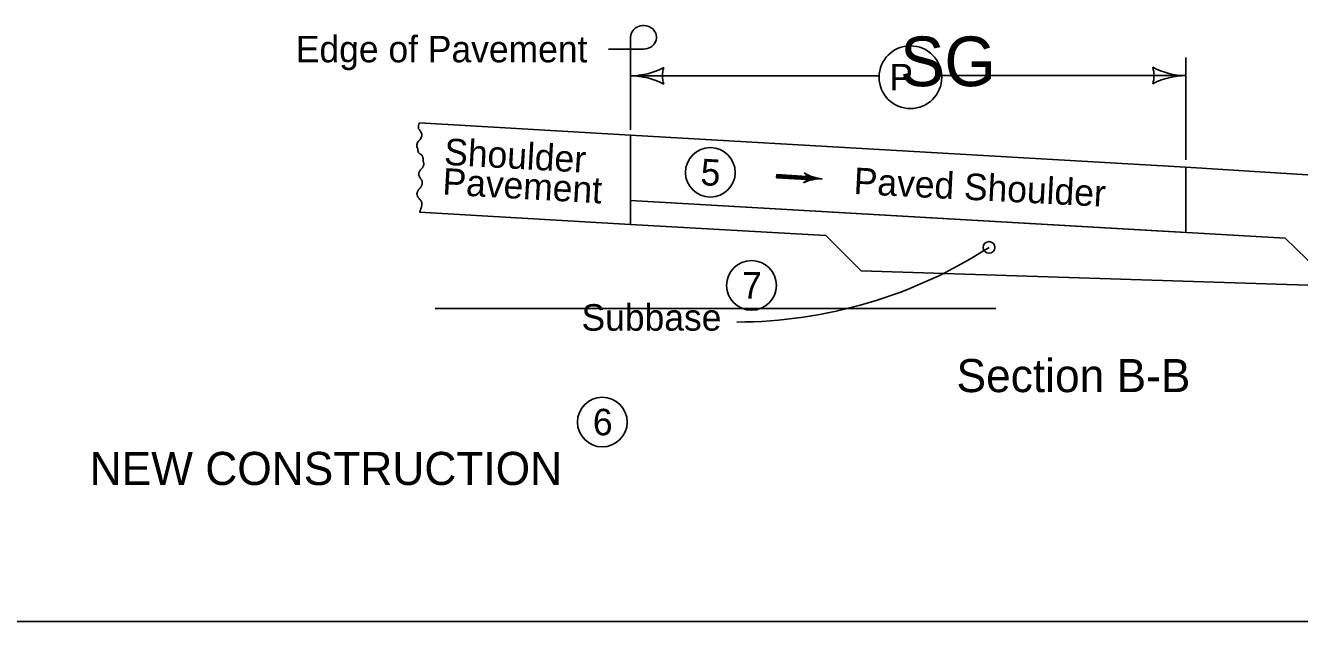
# Model space of a CAD drawing. Extents: x 9538 to 81668, y 7600 to 11751.
# Drawn here: x 18239 to 19008, y 8840 to 9200 of the extents above; entities that cross this region are included whole.
import ezdxf

# ---------------------------------------------------------------- set-up
doc = ezdxf.new("R2010")
doc.units = 0
for name, color, linetype in [('DsnShtMinorGrid13', 7, 'Continuous'), ('DsnShtMinorGrid14', 7, 'Continuous'), ('dsnStdDimension', 7, 'Continuous'), ('dsnStdNameDate', 7, 'Continuous'), ('dsnStdNote', 7, 'Continuous'), ('dsnStdTable', 7, 'Continuous')]:
    doc.layers.add(name, color=color, linetype=linetype)

msp = doc.modelspace()

# ---------------------------------------------------------------- linework, layer by layer
at = {"layer": 'DsnShtMinorGrid13'}
for centre in [(18652.16, 9111.48), (18677.01, 9043.19), (18586.95, 8960.58)]:
    msp.add_circle(centre, 15, dxfattribs=at)
at = {"layer": 'DsnShtMinorGrid14'}
msp.add_circle((18820.4, 9066.08), 3.54, dxfattribs=at)
at = {"layer": 'dsnStdDimension'}
for p, q in [((18939.26, 9119.12), (18939.26, 9180.8)), ((18604.04, 9169.81), (18754.04, 9169.81)), ((18791.86, 9169.96), (18939.26, 9169.96))]:
    msp.add_line(p, q, dxfattribs=at)
msp.add_circle((18772.95, 9168.99), 18.93, dxfattribs=at)
for centre, radius, start, end in [((18604.04, 9212.31), 42.5, 270, 298.07249), ((18604.04, 9127.31), 42.5, 61.92751, 90), ((18639.67, 9169.81), 16.42, 162.26665, 197.73335), ((18903.62, 9169.96), 16.42, 342.26665, 17.73335), ((18939.26, 9212.46), 42.5, 241.92751, 270), ((18939.26, 9127.46), 42.5, 90, 118.07249), ((18667.45, 9303.03), 282.03, 270.13198, 302.84273)]:
    msp.add_arc(centre, radius, start, end, dxfattribs=at)
at = {"layer": 'dsnStdNameDate'}
msp.add_line((19503.11, 8840.02), (17347.53, 8840.02), dxfattribs=at)
at = {"layer": 'dsnStdNote'}
for p, q in [((18604.04, 9173.13), (18604.04, 9193.99)), ((18590.67, 9185.97), (18599.35, 9185.97)), ((18611.85, 9185.97), (18599.35, 9185.97)), ((18604.04, 9137.19), (18604.04, 9173.13)), ((18710.42, 9108.09), (18692.22, 9109.14)), ((18710.32, 9107.15), (18710.32, 9107.15)), ((18710.44, 9109.09), (18710.44, 9109.09))]:
    msp.add_line(p, q, dxfattribs=at)
for points in [[(18710.45, 9109.03), (18692.28, 9110.08), (18692.15, 9108.2), (18710.32, 9107.15), (18710.37, 9108.76), (18692.5, 9109.86), (18692.45, 9108.36), (18709.94, 9107.41), (18710.06, 9108.53), (18692.74, 9109.59), (18692.71, 9108.59), (18709.72, 9107.61), (18709.82, 9108.32), (18692.93, 9109.37), (18692.91, 9108.81), (18709.51, 9107.87)], [(18710.05, 9110.28), (18710.74, 9109.12), (18710.72, 9107.47), (18709.96, 9106.07), (18712.71, 9106.94), (18715.91, 9107.59), (18716.81, 9107.72), (18714.56, 9108.27), (18711.34, 9109.5), (18710.39, 9110.03), (18710.52, 9106.52), (18715.46, 9107.74), (18710.82, 9109.32), (18710.84, 9106.9), (18714.24, 9107.83), (18711.24, 9108.69), (18711, 9107.31), (18713.16, 9107.81), (18711.58, 9108.32), (18711.44, 9107.66), (18712.23, 9107.82)]]:
    msp.add_lwpolyline(points, dxfattribs=at)
for centre, major_axis, start_param, end_param in [((18611.85, 9193.11), (-7.81, 0), 1.570796, 6.283185), ((18706.65, 9108.3), (3.88, 0), 5.202895, 7.237436), ((18718.92, 9087.31), (22.17, 0), 1.537172, 2.061295), ((18721.72, 9127.73), (-22.17, 0), 0.954258, 1.478381)]:
    msp.add_ellipse(centre, major_axis=major_axis, ratio=0.913811, start_param=start_param, end_param=end_param, dxfattribs=at)
at = {"layer": 'dsnStdTable'}
for p, q in [((18476.57, 9141.46), (18604.04, 9134.05)), ((18604.04, 9134.05), (18604.04, 9080.04)), ((18604.04, 9134.05), (18939.18, 9114.56)), ((18939.18, 9114.56), (18604.04, 9134.05)), ((18604.04, 9134.05), (18604.04, 9094.45)), ((18939.18, 9114.56), (19074.01, 9106.17)), ((18939.18, 9075.13), (18939.18, 9114.56)), ((18939.18, 9114.56), (18939.18, 9075.13)), ((18999.18, 9071.67), (18604.04, 9094.45)), ((18604.04, 9094.45), (18939.18, 9075.13)), ((18476.61, 9087.45), (18604.04, 9080.04)), ((18721.88, 9073.24), (18604.04, 9080.04)), ((18721.88, 9073.24), (18743.21, 9052.03)), ((18999.18, 9071.67), (19029.04, 9042.69)), ((18743.21, 9052.03), (19226.56, 9036.24)), ((18485.99, 9029.13), (18824.49, 9029.13))]:
    msp.add_line(p, q, dxfattribs=at)
msp.add_circle((18652.16, 9111.48), 15, dxfattribs=at)
for points in [[(18476.57, 9141.46), (18476.07, 9137.86), (18477.11, 9136.35), (18477.98, 9134.06), (18477.37, 9132), (18475.47, 9129.62), (18474.95, 9127.72), (18475.47, 9125.43), (18476.33, 9123.05), (18477.37, 9122.34), (18478.76, 9119.8), (18478.75, 9118.96)], [(18476.78, 9101.85), (18477, 9102.1), (18477.2, 9102.36), (18477.55, 9102.92), (18477.83, 9103.51), (18477.94, 9103.82), (18478.04, 9104.13), (18478.18, 9104.75), (18478.22, 9105.37), (18478.18, 9105.96), (18478.12, 9106.24), (18478.08, 9106.37), (18478.04, 9106.5), (18477.83, 9106.88), (18477.54, 9107.24), (18477.25, 9107.61), (18477, 9108.01), (18476.86, 9108.29), (18476.72, 9108.57), (18476.46, 9109.15), (18476.26, 9109.71), (18476.18, 9110.01), (18476.13, 9110.3), (18476.12, 9110.43), (18476.12, 9110.56), (18476.27, 9111.33), (18476.48, 9111.85), (18476.74, 9112.36), (18477.18, 9113), (18477.7, 9113.54), (18478.21, 9114.09), (18478.44, 9114.4), (18478.64, 9114.74), (18478.85, 9115.21), (18479.01, 9115.68), (18479.11, 9116.16), (18479.14, 9116.4), (18479.15, 9116.52), (18479.16, 9116.64), (18479.12, 9117.15), (18478.96, 9117.66), (18478.91, 9117.79), (18478.86, 9117.91), (18478.81, 9118.04), (18478.79, 9118.17), (18478.75, 9118.96)], [(18476.78, 9101.85), (18476.57, 9101.62), (18476.32, 9101.38), (18476.09, 9101.14), (18475.91, 9100.87), (18475.77, 9100.59), (18475.63, 9100.3), (18475.37, 9099.73), (18475.25, 9099.45), (18475.16, 9099.16), (18475.09, 9098.87), (18475.06, 9098.72), (18475.04, 9098.57), (18475.05, 9098.06), (18475.18, 9097.54), (18475.39, 9097.02), (18475.65, 9096.51), (18476.09, 9095.88), (18476.61, 9095.33), (18477.12, 9094.78), (18477.35, 9094.48), (18477.55, 9094.14), (18477.95, 9093.19), (18478.06, 9092.72), (18478.07, 9092.24), (18478.04, 9091.95), (18477.99, 9091.66), (18477.94, 9091.37), (18477.87, 9091.09), (18477.55, 9089.94), (18477.37, 9089.33), (18477.18, 9088.73), (18476.96, 9088.14), (18476.83, 9087.85), (18476.69, 9087.57), (18476.61, 9087.45)]]:
    msp.add_spline(points, degree=3, dxfattribs=at)

# ---------------------------------------------------------------- texts
at = {"layer": 'DsnShtMinorGrid13'}
msp.add_text('5', height=16, rotation=356.69973, dxfattribs=at).set_placement((18645.94, 9103.82))
for s, p in [('7', (18671.3, 9035.19)), ('6', (18581.25, 8952.58))]:
    msp.add_text(s, height=16, dxfattribs=at).set_placement(p)
at = {"layer": 'dsnStdDimension'}
for s, height, p in [('SG', 30, (18766.67, 9163.55)), ('P', 16, (18760.24, 9160.99))]:
    msp.add_text(s, height=height, dxfattribs=at).set_placement(p)
at = {"layer": 'dsnStdNote'}
for s, height, p in [('Edge of Pavement', 16, (18401.91, 9177.97)), ('Subbase', 16, (18574.39, 9015.81)), ('Section B-B', 20, (18800.78, 8978.66)), ('NEW CONSTRUCTION', 20, (18277.43, 8922.54))]:
    msp.add_text(s, height=height, dxfattribs=at).set_placement(p)
for s, rotation, p in [('Shoulder', 356.73462, (18491.17, 9116.12)), ('Pavement', 356.73462, (18490.15, 9098.15)), ('Paved Shoulder ', 357.0678, (18738.43, 9098.45))]:
    msp.add_text(s, height=16, rotation=rotation, dxfattribs=at).set_placement(p)

doc.saveas('drawing.dxf')
